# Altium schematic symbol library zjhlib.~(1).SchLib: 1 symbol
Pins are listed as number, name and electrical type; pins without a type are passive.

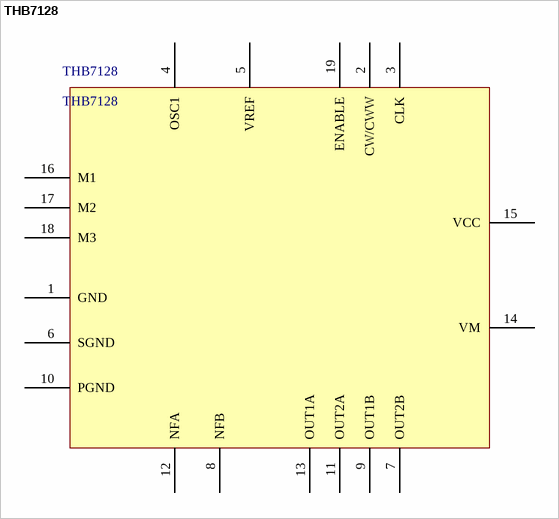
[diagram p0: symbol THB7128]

## THB7128
designator THB7128
pins: 1 GND, 2 CW/CWW, 3 CLK, 4 OSC1, 5 VREF, 6 SGND, 7 OUT2B, 8 NFB, 9 OUT1B, 10 PGND, 11 OUT2A, 12 NFA, 13 OUT1A, 14 VM, 15 VCC, 16 M1, 17 M2, 18 M3, 19 ENABLE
